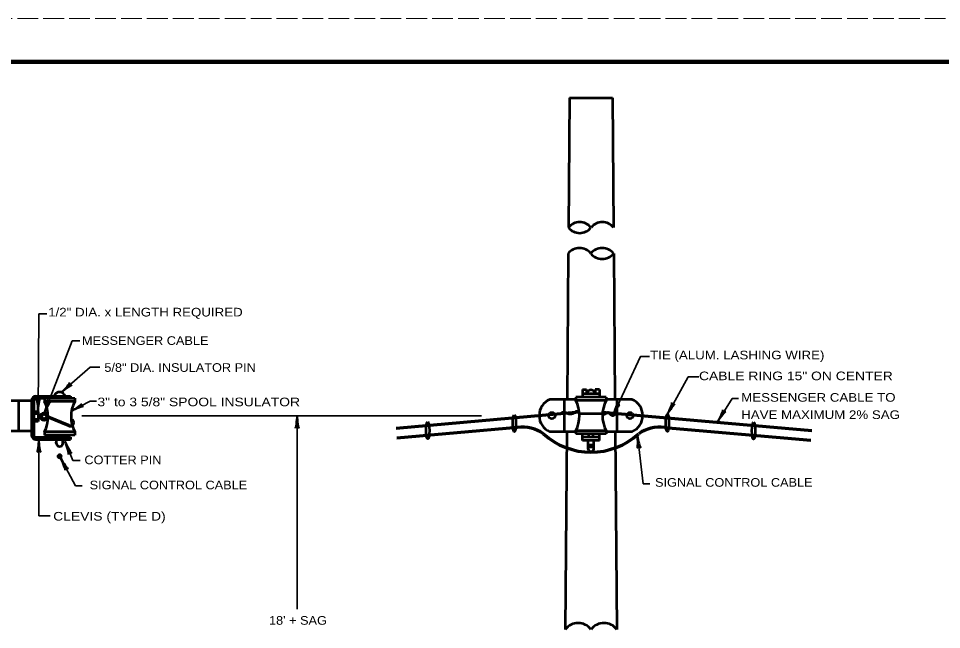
# Model space of a CAD drawing. Extents: x -368 to 312, y -34 to 406.
# Drawn here: x -151.6 to 62, y 264.7 to 406 of the extents above; entities that cross this region are included whole.
import ezdxf
from ezdxf.enums import TextEntityAlignment as Align

# ---------------------------------------------------------------- set-up
doc = ezdxf.new("R2010")
doc.units = 0
doc.header["$LTSCALE"] = 0.8
doc.linetypes.add('LONG_DASHED', pattern=[7.5, 6, -1.5])
doc.layers.add('1', color=7, linetype='Continuous', lineweight=53)
doc.layers.add('61', color=7, linetype='Continuous', lineweight=35)

msp = doc.modelspace()

# ---------------------------------------------------------------- hatches: boundary and pattern name
at = {"layer": '1'}
msp.add_hatch(color=256, dxfattribs=at).paths.add_polyline_path([(-141.6243, 304.7346, 1), (-142.6243, 304.7346, 1)])

# ---------------------------------------------------------------- linework, layer by layer
for p, q in [((-24.1663, 387.6552), (-24.3971, 357.6552)), ((-24.1663, 387.6552), (-14.1663, 387.6552)), ((-14.1663, 387.6552), (-13.9355, 357.6552)), ((-24.4432, 351.6552), (-24.7029, 317.9052)), ((-13.8894, 351.6552), (-13.6297, 317.9052)), ((-147.622, 318.6552), (-139.622, 318.6552)), ((-139.622, 318.6552), (-139.622, 318.1552)), ((-22.6663, 318.4052), (-22.6663, 317.6552)), ((-15.6663, 318.4052), (-22.6663, 318.4052)), ((-21.1663, 320.1552), (-21.1663, 318.4052)), ((-21.1663, 320.1552), (-20.1663, 320.1552)), ((-17.1663, 319.1552), (-21.1663, 319.1552)), ((-20.1663, 320.1552), (-20.1663, 319.1552)), ((-17.1663, 320.1552), (-18.1663, 320.1552)), ((-18.1663, 320.1552), (-18.1663, 319.1552)), ((-17.1663, 320.1552), (-17.1663, 318.4052)), ((-15.6663, 318.4052), (-15.6663, 317.6552)), ((-156.622, 317.6552), (-148.622, 317.6552)), ((-151.622, 317.6552), (-151.622, 310.6552)), ((-148.622, 317.6552), (-148.622, 309.6552)), ((-148.122, 317.6552), (-148.122, 309.6552)), ((-147.622, 318.1552), (-138.622, 318.1552)), ((-145.622, 318.1552), (-145.622, 317.4052)), ((-138.622, 317.4052), (-145.622, 317.4052)), ((-138.622, 318.1552), (-138.622, 317.4052)), ((-22.6663, 317.9052), (-28.6663, 317.9052)), ((-25.2607, 310.4052), (-25.2607, 317.9052)), ((-15.6663, 317.6552), (-22.6663, 317.6552)), ((-9.6663, 317.9052), (-15.6663, 317.9052)), ((-13.0722, 310.4052), (-13.0722, 317.9052)), ((-147.122, 315.0302), (-148.122, 315.0302)), ((-147.122, 314.5302), (-148.122, 314.5302)), ((-147.122, 315.0302), (-147.122, 312.7802)), ((-146.5083, 314.2802), (-147.122, 314.2802)), ((-16.5107, 314.5302), (-21.822, 314.5302)), ((-147.122, 313.2802), (-148.122, 313.2802)), ((-147.122, 312.7802), (-148.122, 312.7802)), ((-146.4985, 313.5302), (-147.122, 313.5302)), ((-156.622, 310.6552), (-148.622, 310.6552)), ((-138.622, 310.4052), (-145.622, 310.4052)), ((-145.622, 310.4052), (-145.622, 309.6552)), ((-138.622, 310.4052), (-138.622, 309.6552)), ((-22.6663, 310.4052), (-28.6663, 310.4052)), ((-24.7606, 310.4052), (-25.1125, 264.6552)), ((-15.6663, 310.6552), (-22.6663, 310.6552)), ((-22.6663, 310.6552), (-22.6663, 309.9052)), ((-15.6663, 309.9052), (-22.6663, 309.9052)), ((-21.1663, 308.4052), (-21.1663, 309.9052)), ((-19.6663, 309.1552), (-19.6663, 309.9052)), ((-18.6663, 309.1552), (-18.6663, 309.9052)), ((-17.1663, 308.4052), (-17.1663, 309.9052)), ((-15.6663, 310.6552), (-15.6663, 309.9052)), ((-9.6663, 310.4052), (-15.6663, 310.4052)), ((-13.5721, 310.4052), (-13.2202, 264.6552)), ((-147.622, 309.1552), (-139.622, 309.1552)), ((-147.622, 308.6552), (-139.622, 308.6552)), ((-138.622, 309.6552), (-145.622, 309.6552)), ((-142.872, 309.1552), (-142.872, 309.6552)), ((-142.872, 307.6552), (-142.872, 308.6552)), ((-141.372, 309.1552), (-141.372, 309.6552)), ((-141.372, 307.6552), (-141.372, 308.6552)), ((-139.622, 309.1552), (-139.622, 308.6552)), ((-17.1663, 309.1552), (-21.1663, 309.1552)), ((-17.1663, 308.4052), (-21.1663, 308.4052)), ((-19.7913, 306.4052), (-19.7913, 308.4052)), ((-18.5413, 306.4052), (-18.5413, 308.4052))]:
    msp.add_line(p, q, dxfattribs=at)
at = {"layer": '1', "lineweight": 35}
for p, q in [((-147.122, 315.0302), (-146.965, 337.6697)), ((-146.965, 337.6697), (-145.0842, 337.6717)), ((-145.6128, 314.8723), (-139.253, 331.4616)), ((-139.253, 331.4616), (-137.4536, 331.432)), ((-141.7106, 319.5652), (-135.0756, 325.3728)), ((-135.0756, 325.3728), (-132.851, 325.374)), ((-1.4977, 314.4453), (3.3444, 323.0881)), ((3.3444, 323.0881), (5.8242, 323.1117)), ((10.1777, 312.8087), (13.4846, 318.1303)), ((13.4846, 318.1303), (14.9635, 318.1148)), ((-136.9885, 314.108), (-44.4885, 314.108)), ((-87.1562, 269.3816), (-87.1562, 314.108)), ((-146.9281, 308.6006), (-146.9281, 290.9645)), ((-142.872, 308.1552), (-143.2256, 308.5087)), ((-142.872, 308.1552), (-143.2256, 307.8016)), ((-141.8422, 304.2587), (-138.4364, 297.9148)), ((-138.4364, 297.9148), (-136.9085, 297.9312)), ((-146.9281, 290.9645), (-144.2969, 290.9645))]:
    msp.add_line(p, q, dxfattribs=at)
at = {"layer": '1', "lineweight": 70}
for p, q in [((-21.851, 314.9162), (-64.2559, 311.2063)), ((-16.4813, 314.9195), (31.9373, 310.6833)), ((-144.7684, 313.9052), (-140.0899, 311.9082)), ((-36.1663, 311.4052), (-64.0597, 308.9648)), ((-2.1293, 311.4052), (31.7412, 308.4418)), ((-19.1663, 307.6552), (-19.1663, 306.6552))]:
    msp.add_line(p, q, dxfattribs=at)
at = {"layer": '1', "lineweight": 35}
for points in [[(-14.0655, 314.2222), (-7.6701, 327.8355), (-5.5878, 327.8355)], [(-139.343, 315.2233), (-135.0902, 317.5038), (-133.5994, 317.5038)], [(-140.7899, 307.9866), (-139.0361, 303.7762), (-137.37, 303.7762)], [(-8.4138, 309.5356), (-7.0752, 298.3772), (-5.5135, 298.3772)]]:
    msp.add_lwpolyline(points, dxfattribs=at)
at = {"layer": '1'}
for centre, radius in [((-145.7129, 313.9155), 0.875), ((-145.7067, 313.9422), 0.5222), ((-28.2033, 314.1502), 0.75), ((-10.1405, 314.1502), 0.75)]:
    msp.add_circle(centre, radius, dxfattribs=at)
at = {"layer": '1', "lineweight": 35}
msp.add_circle((-142.1243, 304.7346), 0.5, dxfattribs=at)
at = {"layer": '1'}
for centre, radius, start, end in [((-21.7817, 355.5698), 3.3465, 38.6004, 141.3996), ((-16.5415, 355.5698), 3.3465, 38.6004, 141.3996), ((-21.7817, 359.743), 3.3465, 218.6004, 321.3996), ((-21.8279, 349.5673), 3.3465, 38.6004, 141.3996), ((-16.5876, 349.5673), 3.3465, 38.6004, 141.3996), ((-16.5876, 353.7405), 3.3465, 218.6004, 321.3996), ((-147.622, 317.6552), 1, 90, 180), ((-142.122, 318.3136), 1.2958, 15.28151, 164.71849), ((-19.1663, 319.2193), 0.8773, 355.80967, 184.19033), ((-147.622, 317.6552), 0.5, 90, 180), ((-152.3711, 313.9052), 7.6027, 332.5894, 27.4106), ((-131.8729, 313.9052), 7.6027, 152.5894, 207.4106), ((-27.086, 314.1552), 4.0694, 112.85129, 247.14871), ((-29.4155, 314.1552), 7.6027, 332.5894, 27.4106), ((-8.9172, 314.1552), 7.6027, 152.5894, 207.4106), ((-11.2578, 314.1552), 4.0694, 292.85129, 67.14871), ((-147.622, 309.6552), 1, 180, 270), ((-147.622, 309.6552), 0.5, 180, 270), ((-142.122, 307.75), 0.756, 187.20763, 352.79237), ((-19.1663, 306.4441), 0.6262, 183.56726, 356.43274), ((-22.1394, 262.4582), 3.7066, 36.66818, 143.33182), ((-16.1734, 262.4582), 3.7066, 36.66818, 143.33182)]:
    msp.add_arc(centre, radius, start, end, dxfattribs=at)
at = {"layer": '1', "lineweight": 70}
for centre, radius, start, end in [((-139.6619, 312.4897), 0.7221, 233.64544, 71.83182), ((-34.8988, 303.7252), 7.7839, 52.55588, 99.37163), ((-19.1663, 322.1345), 16.4486, 228.02939, 311.9706), ((-3.3968, 303.7252), 7.7839, 80.62837, 127.44412)]:
    msp.add_arc(centre, radius, start, end, dxfattribs=at)
at = {"layer": '1', "lineweight": 35}
for centre, radius, start, end in [((-140.9632, 307.9695), 0.467, 108.38064, 151.10471), ((-140.9654, 308.3373), 0.4637, 208.73791, 251.77673), ((-141.0422, 308.1547), 0.2668, 255.19279, 104.80721)]:
    msp.add_arc(centre, radius, start, end, dxfattribs=at)
at = {"layer": '1', "lineweight": 40}
for centre, major_axis, ratio, start_param, end_param in [((-141.0715, 320.4918), (-1.2408, -1.2936), 0.122415, 0.89635335, 3.14159265), ((-141.0715, 320.4918), (-1.2408, -1.2936), 0.122415, 0.89635335, 3.14159265), ((-140.7281, 320.1439), (-1.4374, -1.0247), 0.07063, 3.14071475, 5.41810995), ((-140.7281, 320.1439), (-1.4374, -1.0247), 0.07063, 3.14071475, 5.41810995), ((-147.3907, 316.1233), (0.1438, -1.7867), 0.122415, 0.89635335, 3.14159265), ((-147.3907, 316.1233), (0.1438, -1.7867), 0.122415, 0.89635335, 3.14159265), ((-146.9026, 316.1492), (0.1878, 1.7552), 0.07063, 6.28230741, 8.55970261), ((-146.9026, 316.1492), (0.1878, 1.7552), 0.07063, 6.28230741, 8.55970261), ((-145.4801, 315.9901), (-0.4934, -1.7233), 0.122415, 0.89635335, 3.14159265), ((-145.4801, 315.9901), (-0.4934, -1.7233), 0.122415, 0.89635335, 3.14159265), ((-145.0141, 315.8428), (0.7928, 1.5772), 0.07063, 6.28230741, 8.55970261), ((-145.0141, 315.8428), (0.7928, 1.5772), 0.07063, 6.28230741, 8.55970261), ((-138.5119, 315.9824), (-1.4999, -0.9815), 0.122415, 0.89635335, 3.14159265), ((-138.5119, 315.9824), (-1.4999, -0.9815), 0.122415, 0.89635335, 3.14159265), ((-138.2555, 315.5663), (1.6309, 0.6753), 0.07063, 6.28230741, 8.55970261), ((-138.2555, 315.5663), (1.6309, 0.6753), 0.07063, 6.28230741, 8.55970261), ((-13.8516, 315.3273), (-0.618, -1.6826), 0.122415, 0.89635335, 3.14159265), ((-13.8516, 315.3273), (-0.618, -1.6826), 0.122415, 0.89635335, 3.14159265), ((-13.3975, 315.1464), (-0.9058, -1.5151), 0.07063, 3.14071475, 5.41810995), ((-13.3975, 315.1464), (-0.9058, -1.5151), 0.07063, 3.14071475, 5.41810995), ((-1.2054, 315.5324), (-0.7366, -1.6342), 0.122415, 0.89635335, 3.14159265), ((-1.2054, 315.5324), (-0.7366, -1.6342), 0.122415, 0.89635335, 3.14159265), ((-0.7655, 315.3194), (1.0117, 1.4465), 0.07063, 6.28230741, 8.55970261), ((-0.7655, 315.3194), (1.0117, 1.4465), 0.07063, 6.28230741, 8.55970261), ((-87.3679, 312.9875), (0.1757, 1.7565), 0.07063, 3.14071475, 5.41810995), ((-87.3679, 312.9875), (0.1757, 1.7565), 0.07063, 3.14071475, 5.41810995), ((-86.88, 313.0168), (-0.1562, 1.7857), 0.122415, 0.89635335, 3.14159265), ((-86.88, 313.0168), (-0.1562, 1.7857), 0.122415, 0.89635335, 3.14159265), ((10.5189, 313.8814), (-0.8099, -1.5991), 0.122415, 0.89635335, 3.14159265), ((10.5189, 313.8814), (-0.8099, -1.5991), 0.122415, 0.89635335, 3.14159265), ((10.9488, 313.6488), (1.0763, 1.3992), 0.07063, 6.28230741, 8.55970261), ((10.9488, 313.6488), (1.0763, 1.3992), 0.07063, 6.28230741, 8.55970261), ((-147.1397, 307.4801), (0.1757, 1.7565), 0.07063, 3.14071475, 5.41810995), ((-146.6518, 307.5094), (-0.1562, 1.7857), 0.122415, 0.89635335, 3.14159265), ((-140.5544, 306.8709), (-0.5132, 1.6889), 0.07063, 3.14071475, 5.41810995), ((-140.5544, 306.8709), (-0.5132, 1.6889), 0.07063, 3.14071475, 5.41810995), ((-140.1153, 307.0855), (-0.8308, 1.5884), 0.122415, 0.89635335, 3.14159265), ((-140.1153, 307.0855), (-0.8308, 1.5884), 0.122415, 0.89635335, 3.14159265), ((-8.4904, 308.3979), (-0.0348, 1.7649), 0.07063, 3.14071475, 5.41810995), ((-8.0094, 308.4851), (-0.3677, 1.7544), 0.122415, 0.89635335, 3.14159265), ((-141.4986, 303.1714), (0.6761, -1.6306), 0.07063, 6.28230741, 8.55970261), ((-141.4986, 303.1714), (0.6761, -1.6306), 0.07063, 6.28230741, 8.55970261), ((-141.0826, 303.4279), (-0.9822, 1.4994), 0.122415, 0.89635335, 3.14159265), ((-141.0826, 303.4279), (-0.9822, 1.4994), 0.122415, 0.89635335, 3.14159265)]:
    msp.add_ellipse(centre, major_axis=major_axis, ratio=ratio, start_param=start_param, end_param=end_param, dxfattribs=at)
at = {"layer": '1'}
for centre in [(-36.9029, 312.3807), (-1.4823, 312.4472), (-56.9285, 310.7155), (18.4542, 310.6523)]:
    msp.add_ellipse(centre, major_axis=(0, 1.9674), ratio=0.186637, dxfattribs=at)
for points in [[(-21.822, 314.5302), (-22.0651, 315.0235), (-22.4768, 315.1313), (-22.7514, 315.0038), (-22.9377, 314.9058), (-23.0553, 314.739), (-23.1534, 314.69), (-23.4083, 314.5723), (-23.8986, 314.4644), (-24.281, 314.4742), (-24.7712, 314.7292), (-25.1242, 314.8763), (-25.487, 314.9156), (-25.7027, 314.8763), (-25.8792, 314.7979), (-26.0459, 314.6802), (-26.1832, 314.5429)], [(-16.5107, 314.5302), (-16.2776, 314.4889), (-15.8635, 314.5883), (-15.615, 314.7375), (-15.4162, 314.87), (-15.2507, 314.9197), (-14.9359, 314.7541), (-14.8034, 314.5883), (-14.6212, 314.4061), (-14.555, 314.3398), (-14.3727, 314.2238), (-14.0249, 314.1907), (-13.7765, 314.3067), (-13.5115, 314.5221), (-13.379, 314.6877)]]:
    msp.add_spline(points, degree=3, dxfattribs=at)
at = {"layer": '61', "linetype": 'LONG_DASHED', "lineweight": 13}
msp.add_line((-367.9015, 406.0392), (312.1185, 406.0392), dxfattribs=at)
at = {"layer": '61', "lineweight": 158}
msp.add_lwpolyline([(301.1385, 396.0392), (-337.9015, 396.0392), (-337.9015, -23.9808)], dxfattribs=at)

# ---------------------------------------------------------------- texts
at = {"layer": '1'}
for s, width, p in [('1/2" DIA. x LENGTH REQUIRED', 1.15, (-122.2655, 337.0892)), ('MESSENGER CABLE', 1.1, (-122.3149, 330.5096)), ('TIE (ALUM. LASHING WIRE)', 1.15, (14.6796, 327.1655)), ('5/8" DIA. INSULATOR PIN', 1.1, (-114.247, 324.275)), ('CABLE RING 15" ON CENTER', 1.2, (28.2468, 322.3388)), ('3" to 3 5/8" SPOOL INSULATOR', 1.2, (-109.9309, 316.3134)), ('COTTER PIN', 1.1, (-127.4706, 302.9079)), ('SIGNAL CONTROL CABLE', 1.1, (-116.9456, 297.0964)), ('SIGNAL CONTROL CABLE', 1.1, (13.885, 297.6945)), ('CLEVIS (TYPE D)', 1.2, (-130.59, 289.8597)), ("18' + SAG", 1.1, (-86.9736, 265.7641))]:
    msp.add_text(s, height=2, dxfattribs=dict(at, width=width)).set_placement(p, align=Align.CENTER)
at = {"layer": '1', "width": 1.15}
for s, p in [('MESSENGER CABLE TO', (15.5879, 317.364)), ('HAVE MAXIMUM 2% SAG', (15.5879, 313.364))]:
    msp.add_text(s, height=2, dxfattribs=at).set_placement(p)

doc.saveas('drawing.dxf')
